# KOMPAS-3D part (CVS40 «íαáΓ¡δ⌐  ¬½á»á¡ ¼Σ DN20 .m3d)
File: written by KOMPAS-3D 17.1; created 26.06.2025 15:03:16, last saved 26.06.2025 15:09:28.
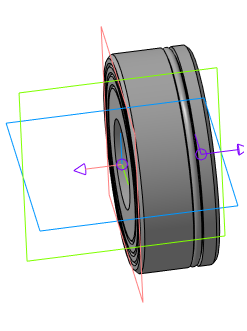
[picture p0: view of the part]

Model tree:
1. Эскиз:1
2. Элемент вращения:1
     Угол 1 = 360
3. Присоединительная точка:1
4. Присоединительная точка:2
